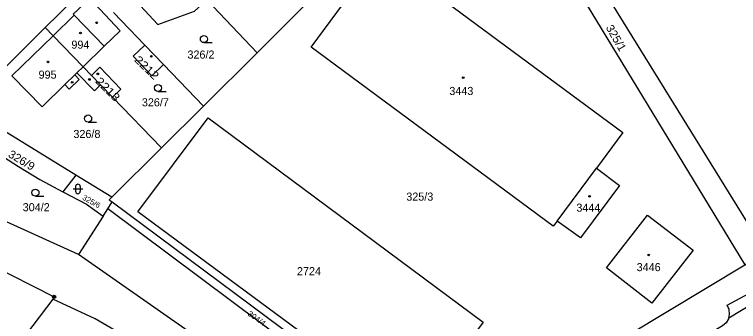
# Model space of a CAD drawing. Extents: x -679733 to -673243, y -1075091 to -1066557.
# Drawn here: x -676172.4 to -676019.9, y -1072340.3 to -1072275.6 of the extents above; entities that cross this region are included whole.
import ezdxf
from ezdxf.enums import TextEntityAlignment as Align

# ---------------------------------------------------------------- set-up
doc = ezdxf.new("R2010")
doc.units = 0
doc.header["$LTSCALE"] = 0.68
for name, color, linetype, lineweight in [('1', 7, 'Continuous', 25), ('3', 7, 'Continuous', 25), ('4', 7, 'Continuous', 13), ('5', 7, 'Continuous', 25), ('8', 7, 'Continuous', 25)]:
    doc.layers.add(name, color=color, linetype=linetype, lineweight=lineweight)
doc.layers.add('2', color=7, linetype='Continuous')

msp = doc.modelspace()

# ---------------------------------------------------------------- linework, layer by layer
at = {"layer": '1'}
for p, q in [((-676121.25, -1072283.67), (-676131.89, -1072272.47)), ((-676182.79, -1072295.17), (-676165.95, -1072278.37)), ((-676164.27, -1072280.1), (-676157.95, -1072286.65)), ((-676141, -1072286.18), (-676144.94, -1072282.06)), ((-676157.95, -1072286.65), (-676156.21, -1072288.45)), ((-676132.59, -1072294.95), (-676141, -1072286.18)), ((-676154.26, -1072290.47), (-676156.21, -1072288.45)), ((-676154.26, -1072290.47), (-676151.77, -1072293.05)), ((-676151.77, -1072293.05), (-676141.46, -1072303.74)), ((-676058.11, -1072319.18), (-676049.83, -1072308.01)), ((-676152.74, -1072316.53), (-676151.84, -1072315.08)), ((-676153.74, -1072318.1), (-676152.74, -1072316.53)), ((-676153.74, -1072318.1), (-676158.9, -1072326.2)), ((-676013.03, -1072334.17), (-676021.95, -1072339.58))]:
    msp.add_line(p, q, dxfattribs=at)
for points in [[(-676014.12, -1072325.69), (-676057.08, -1072256.19), (-676055.87, -1072255.44), (-676066.37, -1072237.96), (-676068.07, -1072234.95), (-676073.26, -1072238.04), (-676072.64, -1072239.08)], [(-676061.63, -1072257.37), (-676018.56, -1072328.36), (-676014.12, -1072325.69)], [(-676058.11, -1072319.18), (-676058.91, -1072320.24), (-676109.91, -1072282.48), (-676095.28, -1072262.72), (-676044.26, -1072300.45), (-676049.83, -1072308.01)], [(-676153.23, -1072265.81), (-676142.19, -1072277.76), (-676134.47, -1072274.92), (-676133.77, -1072274.26), (-676131.89, -1072272.47)], [(-676155.45, -1072271.09), (-676156.97, -1072269.5), (-676165.95, -1072278.37), (-676164.27, -1072280.1)], [(-676157.95, -1072286.65), (-676153.48, -1072282.29), (-676150.14, -1072279.04), (-676156.5, -1072272.2), (-676160.02, -1072275.55), (-676159.8, -1072275.77), (-676164.27, -1072280.1)], [(-676110, -1072272.34), (-676121.25, -1072283.67), (-676132.59, -1072294.95), (-676141.46, -1072303.74), (-676151.88, -1072314.09)], [(-676141, -1072286.18), (-676143.45, -1072288.53), (-676147.39, -1072284.41), (-676144.94, -1072282.06), (-676151.54, -1072275.17)], [(-676164.27, -1072280.1), (-676172.96, -1072288.52), (-676166.6, -1072295.09), (-676161.8, -1072290.4), (-676160.86, -1072291.37), (-676158.76, -1072289.32), (-676159.7, -1072288.36), (-676159.26, -1072287.91), (-676155.57, -1072291.73), (-676154.26, -1072290.47)], [(-676156.21, -1072288.45), (-676154.42, -1072286.71), (-676149.97, -1072291.32), (-676151.77, -1072293.05)], [(-676159.45, -1072309.46), (-676182.79, -1072295.17), (-676184.13, -1072297.57), (-676183.48, -1072298.77)], [(-676179.11, -1072302.82), (-676171.58, -1072307.63), (-676167.05, -1072310.36), (-676162.19, -1072312.97)], [(-676049.83, -1072308.01), (-676044.93, -1072311.62), (-676053.2, -1072322.69), (-676058.11, -1072319.18)], [(-676151.88, -1072314.09), (-676159.45, -1072309.46), (-676162.19, -1072312.97)], [(-676162.19, -1072312.97), (-676157.26, -1072315.61), (-676153.74, -1072318.1)], [(-676151.88, -1072314.09), (-676152.43, -1072314.64), (-676151.84, -1072315.08)], [(-676201.78, -1072315.26), (-676182.36, -1072325.86), (-676164.06, -1072335.1), (-676164.32, -1072335.57)], [(-676151.84, -1072315.08), (-676086.92, -1072363.38), (-676076.81, -1072370.93)], [(-676086.92, -1072363.38), (-676088.01, -1072364.92), (-676152.74, -1072316.53)], [(-676060.65, -1072396.71), (-676088.94, -1072374.82), (-676097.4, -1072369.15), (-676135.11, -1072342.81), (-676158.9, -1072326.2), (-676174.82, -1072318.97)], [(-676058.87, -1072361.92), (-676062.91, -1072364.37), (-676067.19, -1072357.62), (-676018.56, -1072328.36)], [(-676021.95, -1072339.58), (-676021.77, -1072338.78), (-676021.86, -1072337.78), (-676022.24, -1072336.86), (-676014.05, -1072332.41), (-676013.03, -1072334.17)], [(-676118.43, -1072364.57), (-676118.66, -1072365.42), (-676118.36, -1072366.5), (-676117.39, -1072367.63), (-676117.98, -1072368.36), (-676134.65, -1072357.27), (-676133.91, -1072355.2), (-676134.27, -1072353.49), (-676135.43, -1072352.11), (-676137.88, -1072350.38), (-676147.44, -1072344.4), (-676155.37, -1072339.72), (-676164.32, -1072335.57), (-676177.05, -1072352.23)], [(-676021.95, -1072339.58), (-676021.99, -1072339.73), (-676022.47, -1072340.58), (-676023.26, -1072341.22), (-676030.96, -1072345.86), (-676031.91, -1072346.14), (-676032.91, -1072346.21), (-676037.32, -1072348.88)]]:
    msp.add_lwpolyline(points, dxfattribs=at)
for points in [[(-676088.31, -1072360.17), (-676146.39, -1072317.18), (-676131.61, -1072297.37), (-676073.68, -1072340.42)], [(-676029.44, -1072325.28), (-676038.11, -1072336.46), (-676047.68, -1072329.01), (-676039.08, -1072317.88)]]:
    msp.add_lwpolyline(points, close=True, dxfattribs=at)
at = {"layer": '3'}
for p, q in [((-676132.493, -1072281.55), (-676130.743, -1072281.55)), ((-676142.173, -1072291.85), (-676140.423, -1072291.85)), ((-676156.893, -1072298.29), (-676155.143, -1072298.29)), ((-676159.531, -1072311.871), (-676159.531, -1072312.872)), ((-676158.529, -1072312.872), (-676158.529, -1072311.871)), ((-676160.031, -1072312.371), (-676158.029, -1072312.371)), ((-676167.993, -1072313.9), (-676166.243, -1072313.9))]:
    msp.add_line(p, q, dxfattribs=at)
for centre in [(-676132.4929, -1072280.7998), (-676142.1729, -1072291.0998), (-676156.8929, -1072297.5398), (-676167.9929, -1072313.1498)]:
    msp.add_circle(centre, 0.75, dxfattribs=at)
for centre, start, end in [((-676159.03, -1072311.8709), 0, 180), ((-676159.03, -1072312.8709), 180, 359.98789)]:
    msp.add_arc(centre, 0.5, start, end, dxfattribs=at)
at = {"layer": '4'}
for p, q in [((-676153.48, -1072282.29), (-676159.8, -1072275.77)), ((-676159.26, -1072287.91), (-676157.95, -1072286.65)), ((-676161.8, -1072290.4), (-676159.7, -1072288.36))]:
    msp.add_line(p, q, dxfattribs=at)
at = {"layer": '5'}
for centre in [(-676155.0768, -1072277.3692), (-676158.4968, -1072279.5292), (-676143.5568, -1072284.4292), (-676165.3568, -1072285.6092), (-676154.8568, -1072288.1392), (-676077.8668, -1072288.9392), (-676160.2368, -1072289.8992), (-676156.6068, -1072289.2992), (-676051.2568, -1072313.9292), (-676038.8068, -1072326.2892)]:
    msp.add_circle(centre, 0.175, dxfattribs=at)
at = {"layer": '8'}
for radius in [0.335, 0.0203]:
    msp.add_circle((-676164.06, -1072335.0999), radius, dxfattribs=at)

# ---------------------------------------------------------------- texts
at = {"layer": '2'}
for s, height, rotation, width, p in [('325/1', 1.7, 300, 1.05, (-676047.896, -1072278.395)), ('2212', 1.7, 316, 1.2, (-676147.31, -1072285.331)), ('2213', 1.7, 315, 1.2, (-676155.491, -1072289.821)), ('326/9', 1.7, 329, 1.05, (-676173.887, -1072305.508)), ('325/6', 1.14, 331, 1.05, (-676158.206, -1072314.538)), ('304/4', 1.14, 325, 1.1, (-676123.406, -1072338.906))]:
    msp.add_text(s, height=height, rotation=rotation, dxfattribs=dict(at, width=width)).set_placement(p)
for s, p in [('994', (-676160.41, -1072282.83)), ('326/2', (-676135.96, -1072284.92)), ('995', (-676167.32, -1072289.14)), ('3443', (-676080.8, -1072292.58)), ('326/7', (-676145.57, -1072294.97)), ('326/8', (-676159.99, -1072301.64)), ('325/3', (-676089.87, -1072314.84)), ('304/2', (-676170.67, -1072317.07)), ('3444', (-676054.03, -1072317.16)), ('3446', (-676041.34, -1072329.69))]:
    msp.add_text(s, height=1.7, dxfattribs=at).set_placement(p)
msp.add_text('2724', height=1.7, dxfattribs=at).set_placement((-676110.37, -1072330.55), align=Align.CENTER)

doc.saveas('drawing.dxf')
